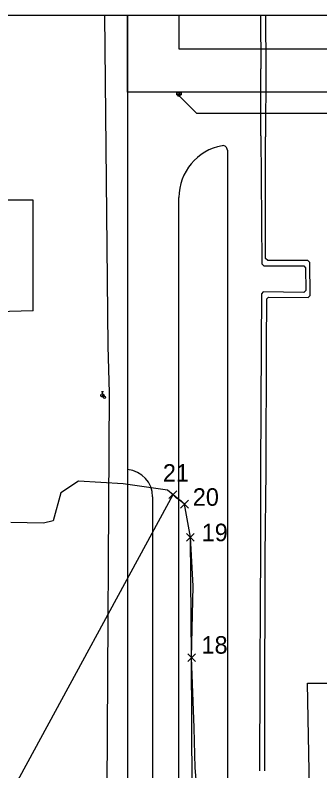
# Model space of a CAD drawing. Extents: x -264095 to -263675, y -1242370 to -1242073.
# Drawn here: x -263972.3 to -263937.5, y -1242158.7 to -1242072.5 of the extents above; entities that cross this region are included whole.
import ezdxf

# ---------------------------------------------------------------- set-up
doc = ezdxf.new("R2010")
doc.units = 0
for name, color, linetype in [('BODY', 7, 'Continuous'), ('KFA_2D_JESTVUJUCE_IS_DSP', 7, 'Continuous'), ('KFA_2D_SITUACIA_DSP', 7, 'Continuous'), ('ORANGE_KABEL_NOVA_TRASA', 7, 'Continuous'), ('POPIS', 7, 'Continuous'), ('Pripojka_NN_pre_ORANGE_vysielac_povodna_trasa', 7, 'Continuous'), ('RAM_NA_TLAC_A3_1-1000', 7, 'Continuous')]:
    doc.layers.add(name, color=color, linetype=linetype)

msp = doc.modelspace()

# ---------------------------------------------------------------- linework, layer by layer
at = {"layer": 'BODY'}
for p, q in [((-263954.757, -1242127.62), (-263953.873, -1242126.736)), ((-263953.873, -1242127.62), (-263954.757, -1242126.736)), ((-263953.426, -1242128.695), (-263952.542, -1242127.811)), ((-263952.542, -1242128.695), (-263953.426, -1242127.811)), ((-263952.748, -1242132.472), (-263951.864, -1242131.588)), ((-263951.864, -1242132.472), (-263952.748, -1242131.588)), ((-263952.608, -1242146.185), (-263951.724, -1242145.301)), ((-263951.724, -1242146.185), (-263952.608, -1242145.301))]:
    msp.add_line(p, q, dxfattribs=at)
at = {"layer": 'KFA_2D_JESTVUJUCE_IS_DSP'}
for p, q in [((-263962.109, -1242072.525), (-263961.708, -1242110.251)), ((-263944.302, -1242072.525), (-263944.281, -1242078.658)), ((-263943.73, -1242072.525), (-263943.726, -1242078.708)), ((-263944.262, -1242086.274), (-263944.281, -1242078.658)), ((-263943.726, -1242078.708), (-263943.748, -1242086.382)), ((-263944.262, -1242086.274), (-263944.165, -1242100.884)), ((-263943.732, -1242100.264), (-263943.748, -1242086.382)), ((-263944.165, -1242100.884), (-263943.933, -1242101.097)), ((-263943.479, -1242100.5), (-263943.732, -1242100.264)), ((-263938.913, -1242100.478), (-263943.479, -1242100.5)), ((-263938.679, -1242100.702), (-263938.913, -1242100.478)), ((-263938.67, -1242104.473), (-263938.679, -1242100.702)), ((-263943.933, -1242101.097), (-263939.391, -1242101.095)), ((-263939.391, -1242101.095), (-263939.173, -1242101.317)), ((-263939.173, -1242101.317), (-263939.148, -1242103.915)), ((-263944.203, -1242104.281), (-263944.247, -1242110.034)), ((-263943.995, -1242104.067), (-263944.203, -1242104.281)), ((-263939.372, -1242104.13), (-263943.995, -1242104.067)), ((-263939.148, -1242103.915), (-263939.372, -1242104.13)), ((-263943.643, -1242104.893), (-263943.683, -1242110.091)), ((-263943.643, -1242104.893), (-263943.421, -1242104.68)), ((-263943.421, -1242104.68), (-263938.898, -1242104.687)), ((-263938.898, -1242104.687), (-263938.67, -1242104.473)), ((-263961.708, -1242110.251), (-263961.582, -1242115.554)), ((-263944.247, -1242110.034), (-263944.306, -1242124.434)), ((-263943.683, -1242110.091), (-263943.723, -1242124.445)), ((-263962.461, -1242115.422), (-263962.21, -1242115.422)), ((-263962.335, -1242115.672), (-263962.335, -1242115.422)), ((-263961.582, -1242115.554), (-263961.999, -1242192.922)), ((-263962.483, -1242115.975), (-263962.188, -1242115.743)), ((-263944.306, -1242124.434), (-263944.326, -1242134.105)), ((-263943.723, -1242124.445), (-263943.809, -1242134.109)), ((-263944.326, -1242134.105), (-263944.369, -1242139.25)), ((-263943.809, -1242134.109), (-263943.839, -1242139.271)), ((-263944.369, -1242139.25), (-263944.386, -1242147.884)), ((-263943.839, -1242139.271), (-263943.869, -1242147.889)), ((-263944.386, -1242147.884), (-263944.412, -1242158.664)), ((-263943.869, -1242147.889), (-263943.853, -1242158.652)), ((-263938.95, -1242148.666), (-263921.69, -1242148.626)), ((-263937.993, -1242200.068), (-263938.95, -1242148.666))]:
    msp.add_line(p, q, dxfattribs=at)
for centre, radius in [((-263962.335, -1242115.859), 0.188), ((-263962.11, -1242116.077), 0.125)]:
    msp.add_circle(centre, radius, dxfattribs=at)
at = {"layer": 'KFA_2D_SITUACIA_DSP'}
for p, q in [((-263959.468, -1242072.525), (-263959.468, -1242179.482)), ((-263959.468, -1242076.382), (-263959.468, -1242072.525)), ((-263953.617, -1242072.525), (-263953.617, -1242076.382)), ((-263959.468, -1242081.307), (-263959.468, -1242076.382)), ((-263953.617, -1242076.382), (-263929.58, -1242076.382)), ((-263953.617, -1242081.307), (-263959.468, -1242081.307)), ((-263953.868, -1242081.597), (-263953.868, -1242081.307)), ((-263953.868, -1242081.307), (-263953.368, -1242081.307)), ((-263953.368, -1242081.597), (-263953.868, -1242081.307)), ((-263953.368, -1242081.597), (-263953.868, -1242081.307)), ((-263953.868, -1242081.307), (-263953.868, -1242081.597)), ((-263953.368, -1242081.597), (-263953.868, -1242081.597)), ((-263953.868, -1242081.597), (-263953.368, -1242081.597)), ((-263953.618, -1242081.697), (-263951.618, -1242083.697)), ((-263929.58, -1242081.307), (-263953.617, -1242081.307)), ((-263953.547, -1242081.768), (-263951.618, -1242083.697)), ((-263953.368, -1242081.307), (-263953.368, -1242081.597)), ((-263951.618, -1242083.697), (-263918.806, -1242083.697)), ((-263948.093, -1242087.901), (-263948.093, -1242241.458)), ((-263970.24, -1242093.63), (-263975.68, -1242093.61)), ((-263970.22, -1242106.22), (-263970.24, -1242093.63)), ((-263953.617, -1242244.458), (-263953.617, -1242093.307)), ((-263970.22, -1242106.22), (-263975.57, -1242106.38)), ((-263959.468, -1242124.318), (-263959.468, -1242124.318)), ((-263956.618, -1242127.418), (-263956.618, -1242162.449))]:
    msp.add_line(p, q, dxfattribs=at)
msp.add_circle((-263953.618, -1242081.697), 0.1, dxfattribs=at)
for centre, radius, start, end in [((-263947.634, -1242093.3), 5.983, 100.0694, 180.06602), ((-263948.593, -1242087.901), 0.5, 0, 100.0694), ((-263959.738, -1242127.427), 3.12, 0.1518, 85.03626)]:
    msp.add_arc(centre, radius, start, end, dxfattribs=at)
at = {"layer": 'ORANGE_KABEL_NOVA_TRASA'}
msp.add_line((-263952.04, -1242175.201), (-263952.166, -1242145.743), dxfattribs=at)
msp.add_lwpolyline([(-263952.166, -1242145.743), (-263952.306, -1242132.03), (-263952.984, -1242128.253), (-263954.315, -1242127.178)], dxfattribs=at)
at = {"layer": 'POPIS'}
msp.add_line((-263954.315, -1242127.178), (-263975.069, -1242165.345), dxfattribs=at)
at = {"layer": 'Pripojka_NN_pre_ORANGE_vysielac_povodna_trasa'}
msp.add_lwpolyline([(-263951.418, -1242162.319), (-263951.777, -1242158.32), (-263951.889, -1242153.754), (-263952.166, -1242145.743), (-263951.997, -1242137.606), (-263952.306, -1242132.03), (-263952.984, -1242128.253), (-263954.937, -1242126.676), (-263959.96, -1242125.928), (-263965.073, -1242125.625), (-263967.075, -1242126.957), (-263967.969, -1242130.142), (-263969.056, -1242130.434), (-263972.787, -1242130.347)], dxfattribs=at)
at = {"layer": 'RAM_NA_TLAC_A3_1-1000'}
msp.add_lwpolyline([(-264095.114, -1242072.525), (-263675.114, -1242072.525), (-263675.114, -1242369.525), (-264095.114, -1242369.525)], close=True, dxfattribs=at)

# ---------------------------------------------------------------- texts
at = {"layer": 'BODY'}
for s, p in [('21', (-263955.447, -1242125.698)), ('20', (-263952.035, -1242128.442)), ('19', (-263951.021, -1242132.479)), ('18', (-263951.041, -1242145.296))]:
    msp.add_text(s, height=2, dxfattribs=at).set_placement(p)

doc.saveas('drawing.dxf')
